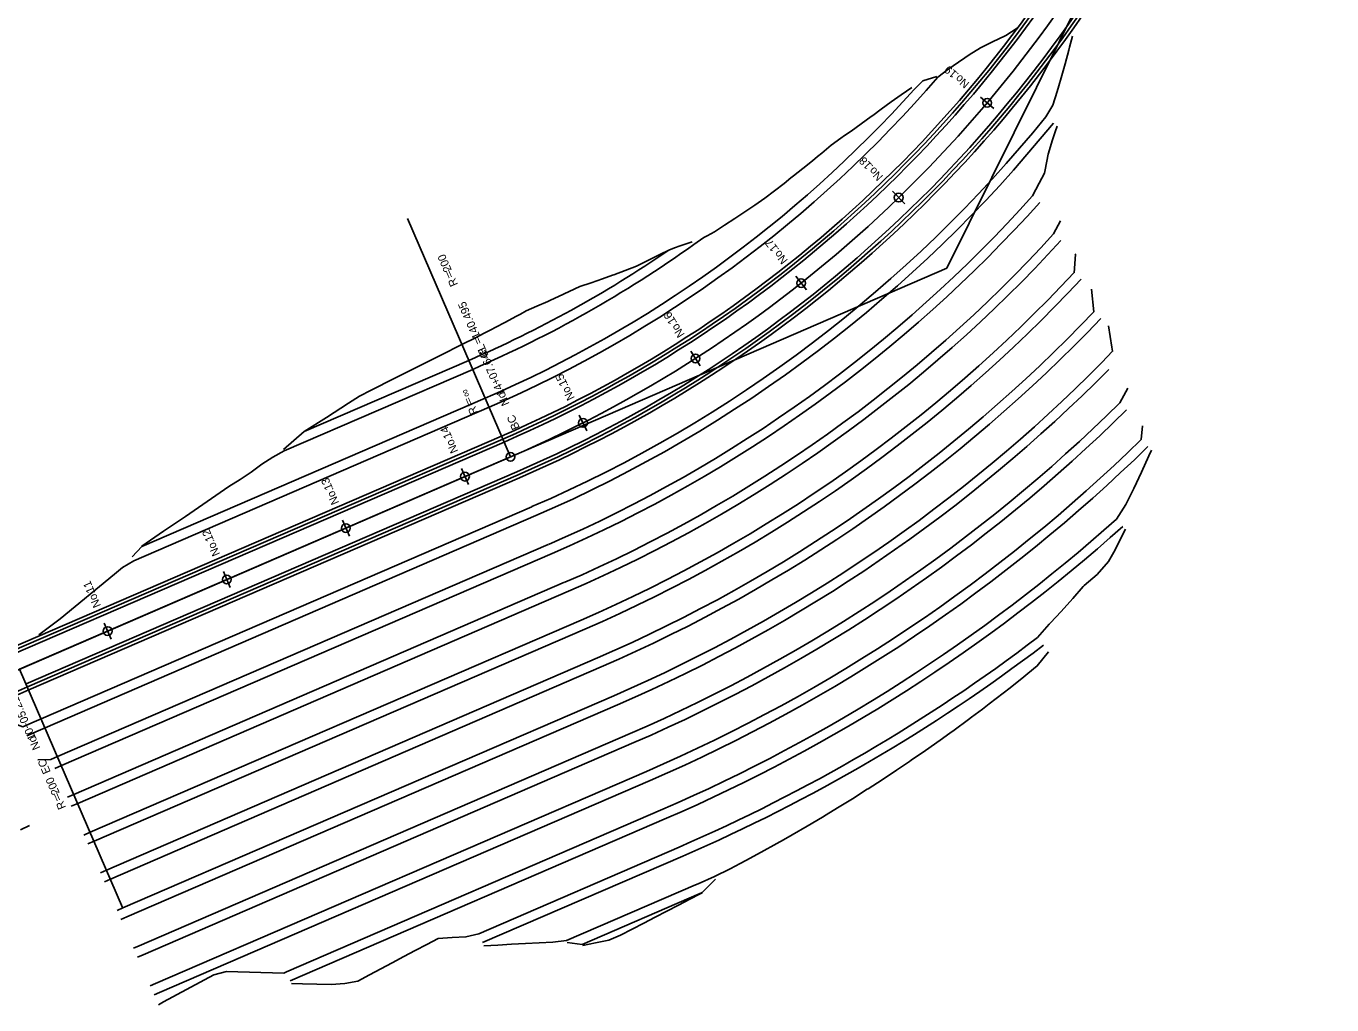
# Model space of a CAD drawing. Extents: x 46574 to 46965, y 10694 to 11089.
# Drawn here: x 46754.5 to 46955.8, y 10790.5 to 10941.4 of the extents above; entities that cross this region are included whole.
import ezdxf

# ---------------------------------------------------------------- set-up
doc = ezdxf.new("R2010")
doc.units = 0
for name, color, linetype in [('Default', 7, 'Continuous'), ('作業レイヤ1', 7, 'Continuous'), ('地形_土崖 コンクリート、堅固な石積等斜面（地理院地図Vector）', 7, 'Continuous'), ('建物_普通建物_普通建物（地理院地図Vector）', 7, 'Continuous'), ('建物_普通建物_普通建物（外周線）（地理院地図Vector）', 7, 'Continuous'), ('河川_通常部（地理院地図Vector）', 7, 'Continuous'), ('現況_地形_三角形_頂点', 7, 'Continuous'), ('等高線等深線_等高線_主曲線通常部（地理院地図Vector）', 7, 'Continuous'), ('道路_通常部_通常部（地理院地図Vector）', 7, 'Continuous')]:
    doc.layers.add(name, color=color, linetype=linetype)

msp = doc.modelspace()

# ---------------------------------------------------------------- linework, layer by layer
at = {"layer": 'Default'}
for p, q in [((46896.47, 10904.04), (46955.82, 11023.71)), ((46902.68, 10929.54), (46902.68, 10929.54)), ((46889.03, 10914.93), (46889.03, 10914.93)), ((46829.19, 10874.97), (46813.33, 10911.69)), ((46730.82, 10832.46), (46896.47, 10904.04)), ((46874, 10901.75), (46874, 10901.75)), ((46857.72, 10890.14), (46857.72, 10890.14)), ((46840.37, 10880.21), (46840.37, 10880.21)), ((46753.52, 10842.27), (46829.19, 10874.97)), ((46829.19, 10874.97), (46829.19, 10874.97)), ((46822.17, 10871.93), (46822.17, 10871.93)), ((46803.81, 10864), (46803.81, 10864)), ((46785.45, 10856.07), (46785.45, 10856.07)), ((46767.09, 10848.13), (46767.09, 10848.13)), ((46753.52, 10842.27), (46769.39, 10805.55))]:
    msp.add_line(p, q, dxfattribs=at)
for centre in [(46902.68, 10929.54), (46889.03, 10914.93), (46874, 10901.75), (46857.72, 10890.14), (46840.37, 10880.21), (46829.19, 10874.97), (46822.17, 10871.93), (46803.81, 10864), (46785.45, 10856.07), (46767.09, 10848.13)]:
    msp.add_circle(centre, 0.675, dxfattribs=at)
msp.add_arc((46749.86, 11058.56), 200, 293.3699, 333.6189, dxfattribs=at)
msp.add_arc((46749.86, 11058.56), 200, 293.3699, 333.6189, dxfattribs=at)
at = {"layer": '作業レイヤ1'}
msp.add_line((46753.52, 10842.27), (46829.19, 10874.97), dxfattribs=at)
msp.add_arc((46749.86, 11058.56), 200, 293.3699, 333.6189, dxfattribs=at)
at = {"layer": '地形_土崖 コンクリート、堅固な石積等斜面（地理院地図Vector）'}
for p, q in [((46752.33, 10845.02), (46828, 10877.72)), ((46754.71, 10839.52), (46830.38, 10872.21))]:
    msp.add_line(p, q, dxfattribs=at)
for centre, radius, start, end in [((46749.86, 11058.56), 197, 293.3699, 333.5778), ((46749.86, 11058.56), 203, 293.3699, 333.5778), ((46832.86, 10658.68), 197, 113.3699, 127.4678)]:
    msp.add_arc(centre, radius, start, end, dxfattribs=at)
at = {"layer": '建物_普通建物_普通建物（地理院地図Vector）'}
for p, q in [((46752.53, 10844.57), (46828.2, 10877.26)), ((46754.52, 10839.98), (46830.18, 10872.67))]:
    msp.add_line(p, q, dxfattribs=at)
for radius in [197.5, 202.5]:
    msp.add_arc((46749.86, 11058.56), radius, 293.3699, 333.5778, dxfattribs=at)
at = {"layer": '建物_普通建物_普通建物（外周線）（地理院地図Vector）'}
for p, q in [((46752.14, 10845.48), (46827.8, 10878.18)), ((46754.91, 10839.06), (46830.58, 10871.76))]:
    msp.add_line(p, q, dxfattribs=at)
for centre, radius, start, end in [((46749.86, 11058.56), 196.5, 293.3699, 333.5778), ((46749.86, 11058.56), 203.5, 293.3699, 333.5778), ((46832.86, 10658.68), 196.5, 113.3699, 127.4678)]:
    msp.add_arc(centre, radius, start, end, dxfattribs=at)
at = {"layer": '現況_地形_三角形_頂点'}
for p, q in [((46912.92, 10909.32), (46913.96, 10911.36)), ((46919.1, 10897.33), (46918.77, 10900.84)), ((46923.12, 10883.29), (46924.34, 10885.56)), ((46926.42, 10877.63), (46926.63, 10879.74)), ((46753.67, 10817.48), (46755.03, 10818.18)), ((46795.24, 10794.23), (46853.25, 10819.29)), ((46824.88, 10800.12), (46855.77, 10813.46))]:
    msp.add_line(p, q, dxfattribs=at)
for points in [[(46895.05, 10933.47), (46896.63, 10934.65), (46898.26, 10935.79), (46899.23, 10936.47), (46899.92, 10936.92), (46901.67, 10938), (46903.59, 10938.96), (46904.37, 10939.35), (46905.53, 10939.93), (46907.31, 10941.05)], [(46911.71, 10927.37), (46912.79, 10929.17), (46913.47, 10931.28), (46913.73, 10932.13), (46914.11, 10933.39), (46914.71, 10935.52), (46915.28, 10937.66), (46915.39, 10938.11), (46915.82, 10939.79)], [(46891.41, 10931.59), (46892.75, 10932.94), (46894.92, 10933.59)], [(46857.47, 10907.71), (46858.99, 10908.77), (46859.49, 10909.04), (46860.64, 10909.66), (46862.2, 10910.68), (46863.75, 10911.7), (46863.93, 10911.82), (46865.31, 10912.73), (46866.85, 10913.78), (46868.39, 10914.84), (46869.89, 10915.95), (46871.36, 10917.1), (46872.43, 10917.95), (46872.82, 10918.26), (46874.28, 10919.43), (46875.73, 10920.61), (46876.52, 10921.25), (46877.18, 10921.8), (46878.61, 10923), (46880.14, 10924.1), (46880.69, 10924.49), (46881.7, 10925.19), (46883.25, 10926.3), (46884.8, 10927.41), (46885.05, 10927.59), (46886.34, 10928.54), (46887.88, 10929.68), (46889.4, 10930.78), (46891.07, 10931.89)], [(46909.68, 10915.2), (46910.7, 10917.16), (46911.5, 10918.69), (46911.6, 10919.22), (46912.06, 10921.62), (46912.74, 10923.81), (46913.18, 10925.07), (46913.48, 10925.94)], [(46797.38, 10878.89), (46800.8, 10881.06), (46804.21, 10883.24), (46805.92, 10884.33), (46807.7, 10885.25), (46811.28, 10887.05), (46814.86, 10888.84), (46818.44, 10890.64), (46821.71, 10892.29), (46821.99, 10892.43), (46823.61, 10893.24), (46825.23, 10894.07), (46826.25, 10894.59), (46826.83, 10894.9), (46828.44, 10895.74), (46830.03, 10896.6), (46830.73, 10896.98), (46831.61, 10897.47), (46833.27, 10898.2), (46834.93, 10898.94), (46835.35, 10899.13), (46836.58, 10899.69), (46838.23, 10900.44), (46839.88, 10901.21), (46841.63, 10901.81), (46843.38, 10902.41), (46844.91, 10902.96), (46845.14, 10903.03), (46846.89, 10903.67), (46848.62, 10904.36), (46849.75, 10904.91), (46850.28, 10905.17), (46851.93, 10906), (46852.3, 10906.19), (46853.58, 10906.84)], [(46853.59, 10906.83), (46854.45, 10907.17), (46855.37, 10907.48), (46857.19, 10908.11)], [(46916.07, 10903.36), (46916.27, 10906.18), (46916.24, 10906.28)], [(46920.35, 10889.51), (46922.01, 10891.24), (46921.91, 10891.89), (46921.38, 10895.16)], [(46794.21, 10876.13), (46795.79, 10877.51), (46797.39, 10878.87), (46822.77, 10889.84)], [(46772.34, 10861.19), (46775.71, 10863.5), (46779.07, 10865.8), (46782.43, 10868.11), (46785.79, 10870.41), (46787.49, 10871.51), (46789.2, 10872.62), (46790.85, 10873.84), (46792.55, 10874.93), (46794.31, 10875.91), (46823.36, 10888.46)], [(46756.46, 10847.54), (46758.1, 10848.77), (46759.74, 10850.04), (46768.15, 10856.92), (46769.39, 10857.94), (46771.13, 10858.97), (46825.88, 10882.63)], [(46770.87, 10859.56), (46772.37, 10861.14), (46825.28, 10884.01)], [(46922.61, 10865.39), (46924.08, 10867.62), (46924.74, 10868.98), (46925.28, 10870.12), (46926.46, 10872.63), (46927.59, 10875.13), (46928.01, 10876)], [(46748.81, 10830.92), (46749, 10834.99), (46751.14, 10834.44), (46751.44, 10834.35), (46754.02, 10833.36), (46755.77, 10834.14), (46756.84, 10834.61), (46832.5, 10867.3)], [(46754.63, 10831.99), (46756.37, 10832.77), (46757.43, 10833.23), (46833.1, 10865.93)], [(46910.46, 10847.14), (46912.24, 10849.18), (46912.45, 10849.4), (46914.07, 10851.14), (46915.86, 10853.13), (46917.49, 10854.98), (46917.63, 10855.14), (46919.64, 10856.85), (46921.39, 10858.86), (46922.39, 10860.64), (46922.74, 10861.3), (46924.02, 10863.81)], [(46756.3, 10828.3), (46758.32, 10828.33), (46759.35, 10828.78), (46835.02, 10861.47)], [(46758.92, 10826.95), (46759.95, 10827.4), (46835.62, 10860.1)], [(46760.87, 10822.51), (46761.87, 10822.95), (46837.54, 10855.65)], [(46761.48, 10821.14), (46762.47, 10821.57), (46838.14, 10854.27)], [(46763.43, 10816.7), (46764.39, 10817.12), (46840.06, 10849.82)], [(46764.03, 10815.33), (46764.99, 10815.74), (46840.66, 10848.44)], [(46825.09, 10799.63), (46827.22, 10799.75), (46829.35, 10799.86), (46831.48, 10799.98), (46833.61, 10800.09), (46835.74, 10800.21), (46837.82, 10800.43), (46857.69, 10809.01), (46858.13, 10809.2), (46860.62, 10810.3), (46863.06, 10811.51), (46864.58, 10812.31), (46865.46, 10812.78), (46867.85, 10814.07), (46870.23, 10815.39), (46871.28, 10815.98), (46872.59, 10816.73), (46874.94, 10818.09), (46877.28, 10819.47), (46877.87, 10819.83), (46879.6, 10820.88), (46881.9, 10822.3), (46884.19, 10823.75), (46884.34, 10823.84), (46886.47, 10825.22), (46888.72, 10826.71), (46890.68, 10828.03), (46890.97, 10828.22), (46893.19, 10829.75), (46895.41, 10831.31), (46896.91, 10832.38), (46897.6, 10832.88), (46899.78, 10834.48), (46900.27, 10834.84), (46901.94, 10836.09), (46903, 10836.9), (46904.08, 10837.73), (46906.21, 10839.39), (46908.32, 10841.06), (46908.96, 10841.58), (46910.41, 10842.76), (46912.14, 10844.93)], [(46765.98, 10810.89), (46766.91, 10811.29), (46842.58, 10843.99)], [(46766.59, 10809.51), (46767.51, 10809.91), (46843.17, 10842.61)], [(46768.54, 10805.07), (46769.43, 10805.46), (46845.1, 10838.16)], [(46769.14, 10803.7), (46770.02, 10804.08), (46845.69, 10836.78)], [(46771.09, 10799.26), (46771.95, 10799.63), (46847.62, 10832.33)], [(46771.7, 10797.88), (46772.54, 10798.25), (46848.21, 10830.95)], [(46773.65, 10793.44), (46774.47, 10793.8), (46850.14, 10826.5)], [(46774.25, 10792.07), (46775.06, 10792.43), (46850.73, 10825.12)], [(46774.93, 10790.53), (46775.69, 10790.97), (46783.46, 10795.13), (46785.4, 10795.68), (46794.23, 10795.43), (46794.64, 10795.6), (46852.65, 10820.67)], [(46795.41, 10793.84), (46797.11, 10793.79), (46799.32, 10793.73), (46801.53, 10793.66), (46803.65, 10793.8), (46805.66, 10794.18), (46807.43, 10795.13), (46809.2, 10796.07), (46810.97, 10797.01), (46812.74, 10797.96), (46814.51, 10798.9), (46816.29, 10799.84), (46818.06, 10800.77), (46820.19, 10800.89), (46822.32, 10801.01), (46824.29, 10801.49), (46855.17, 10814.84)], [(46837.94, 10800.15), (46840.25, 10799.84), (46858.29, 10807.64), (46858.73, 10807.83), (46860.79, 10809.92)], [(46840.32, 10799.69), (46842.32, 10800.09), (46844.33, 10800.48), (46846.17, 10801.26), (46847.95, 10802.19), (46849.73, 10803.12), (46851.51, 10804.04), (46853.29, 10804.97), (46855.07, 10805.9), (46856.84, 10806.82), (46858.31, 10807.58), (46858.74, 10807.8)]]:
    msp.add_lwpolyline(points, dxfattribs=at)
for radius, end in [(191.65, 319.2538), (190.15, 318.1079), (208.35, 320.9727), (209.85, 320.9727), (214.7, 318.1079), (216.2, 318.1079), (221.05, 317.535), (183.8, 304.3569), (185.3, 305.5028), (222.55, 317.535), (227.4, 316.962), (228.9, 316.962), (233.75, 316.389), (235.25, 316.389), (240.1, 315.2431), (241.6, 315.2431), (246.45, 314.6702), (247.95, 314.6702), (252.8, 314.2994), (254.3, 314.2994), (259.15, 311.8054), (260.65, 311.8054), (265.5, 307.2217), (267, 307.2217)]:
    msp.add_arc((46749.86, 11058.56), radius, 293.3699, end, dxfattribs=at)
at = {"layer": '等高線等深線_等高線_主曲線通常部（地理院地図Vector）'}
msp.add_line((46753.52, 10842.27), (46829.19, 10874.97), dxfattribs=at)
msp.add_arc((46749.86, 11058.56), 200, 293.3699, 333.6189, dxfattribs=at)
at = {"layer": '道路_通常部_通常部（地理院地図Vector）'}
for p, q in [((46901.65, 10930.41), (46903.71, 10928.67)), ((46888.09, 10915.9), (46889.97, 10913.96)), ((46873.16, 10902.81), (46874.84, 10900.69)), ((46857, 10891.28), (46858.45, 10889.01)), ((46839.76, 10881.42), (46840.98, 10879.01)), ((46821.64, 10873.17), (46822.71, 10870.7)), ((46803.28, 10865.24), (46804.35, 10862.76)), ((46784.92, 10857.31), (46785.99, 10854.83)), ((46766.56, 10849.37), (46767.63, 10846.9))]:
    msp.add_line(p, q, dxfattribs=at)

# ---------------------------------------------------------------- texts
at = {"layer": 'Default'}
for s, p in [('200', (46820.15, 10903.78)), ('R＝', (46821.11, 10901.54)), ('140.495', (46824.59, 10893.49)), ('CL＝', (46825.88, 10890.51)), ('14+07.648', (46828.4, 10884.68)), ('R＝∞', (46824.2, 10881.8)), ('BC\u3000No.', (46830.65, 10879.46)), ('10+05.217', (46756.07, 10831.65)), ('EC\u3000No.', (46758.33, 10826.43)), ('200', (46759.72, 10823.2)), ('R＝', (46760.69, 10820.96))]:
    msp.add_text(s, height=1.25, rotation=113.3699, dxfattribs=at).set_placement(p)
at = {"layer": '河川_通常部（地理院地図Vector）'}
for s, rotation, p in [('19', 139.8268, (46898.16, 10934.17)), ('No.', 139.8268, (46900.03, 10932.6)), ('18', 134.0972, (46885, 10919.99)), ('No.', 134.0972, (46886.7, 10918.24)), ('17', 128.3676, (46870.49, 10907.19)), ('No.', 128.3676, (46872.01, 10905.28)), ('16', 122.638, (46854.78, 10895.9)), ('No.', 122.638, (46856.09, 10893.85)), ('15', 116.9085, (46838.02, 10886.24)), ('No.', 116.9085, (46839.12, 10884.06)), ('14', 113.3699, (46820.19, 10878.09)), ('No.', 113.3699, (46821.16, 10875.85)), ('13', 113.3699, (46801.83, 10870.16)), ('No.', 113.3699, (46802.8, 10867.92)), ('12', 113.3699, (46783.47, 10862.22)), ('No.', 113.3699, (46784.44, 10859.99)), ('11', 113.3699, (46765.11, 10854.29)), ('No.', 113.3699, (46766.08, 10852.05))]:
    msp.add_text(s, height=1.25, rotation=rotation, dxfattribs=at).set_placement(p)

doc.saveas('drawing.dxf')
